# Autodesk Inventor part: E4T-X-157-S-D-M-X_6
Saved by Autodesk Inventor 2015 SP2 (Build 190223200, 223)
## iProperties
Created: 2016-05
Part Number: E4T-X-157-S-D-M-X_6
Material: Allgemein
Document SubType Name: Modeling
Designer: ryll
Density: 1 g/cm^3
Appearance: Vorgabe
Author: ryll
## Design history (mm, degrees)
node "E4T-X-157-S-D-M-X_61"
node "E4T-X-157-S-D-M-X_6"
node "Basis1"
